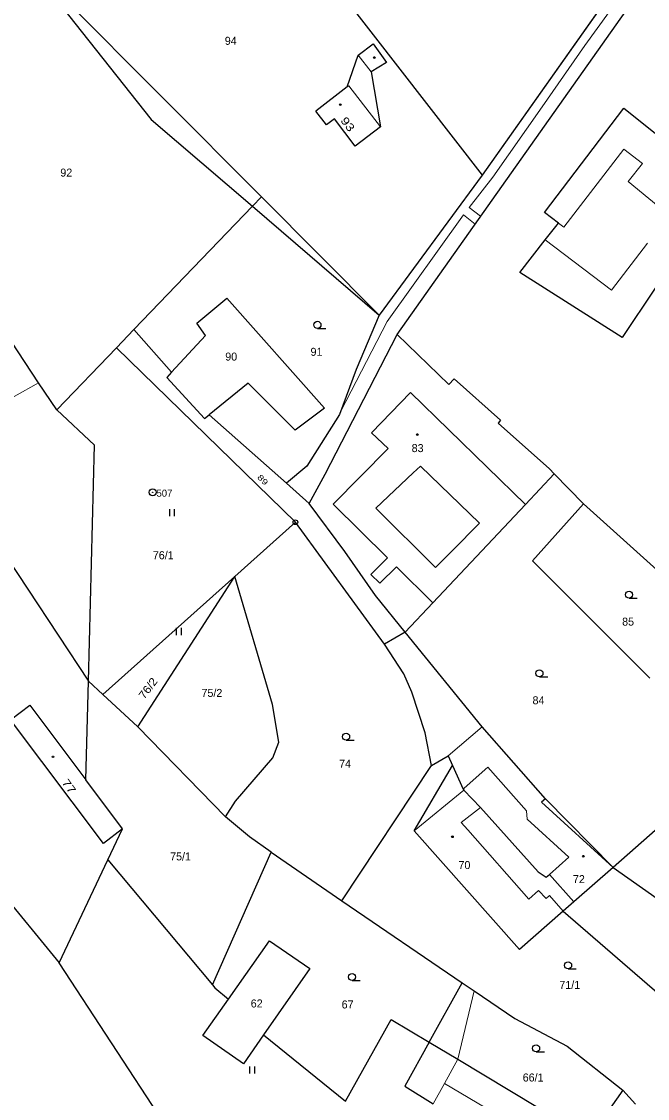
# Model space of a CAD drawing. Extents: x -504006 to -501322, y -1128098 to -1124665.
# Drawn here: x -502824.9 to -502691.9, y -1126531.9 to -1126303.1 of the extents above; entities that cross this region are included whole.
import ezdxf
from ezdxf.enums import TextEntityAlignment as Align

# ---------------------------------------------------------------- set-up
doc = ezdxf.new("R2010")
doc.units = 0
doc.header["$LTSCALE"] = 0.68
for name, color, linetype, lineweight in [('1', 7, 'Continuous', 25), ('13', 7, 'Continuous', 13), ('3', 7, 'Continuous', 25), ('4', 7, 'Continuous', 13), ('5', 7, 'Continuous', 25), ('8', 7, 'Continuous', 25)]:
    doc.layers.add(name, color=color, linetype=linetype, lineweight=lineweight)
doc.layers.add('2', color=7, linetype='Continuous')

msp = doc.modelspace()

# ---------------------------------------------------------------- linework, layer by layer
at = {"layer": '1'}
for p, q in [((-502765.38, -1126286.27), (-502727.05, -1126335.75)), ((-502824.6, -1126289.43), (-502797.35, -1126323.91)), ((-502745.09, -1126369.61), (-502691.94, -1126294.4)), ((-502699.22, -1126296.35), (-502727.05, -1126335.75)), ((-502821.24, -1126379.86), (-502870.11, -1126306.48)), ((-502753.34, -1126310.27), (-502750.18, -1126307.85)), ((-502750.18, -1126307.85), (-502747.34, -1126311.8)), ((-502755.67, -1126317), (-502753.34, -1126310.27)), ((-502747.34, -1126311.8), (-502750.64, -1126313.8)), ((-502750.64, -1126313.8), (-502748.65, -1126325.49)), ((-502755.67, -1126317), (-502762.37, -1126322.15)), ((-502760.1, -1126325.1), (-502762.37, -1126322.15)), ((-502713.8, -1126343.71), (-502696.91, -1126321.52)), ((-502696.91, -1126321.52), (-502675.99, -1126338.4)), ((-502797.35, -1126323.91), (-502775.83, -1126342.38)), ((-502758.41, -1126323.8), (-502760.1, -1126325.1)), ((-502753.97, -1126329.58), (-502758.41, -1126323.8)), ((-502748.65, -1126325.49), (-502753.97, -1126329.58)), ((-502727.05, -1126335.75), (-502748.9, -1126365.5)), ((-502801, -1126368.56), (-502775.83, -1126342.38)), ((-502775.83, -1126342.38), (-502748.9, -1126365.5)), ((-502710.8, -1126345.95), (-502713.8, -1126343.71)), ((-502713.68, -1126349.52), (-502710.8, -1126345.95)), ((-502944.94, -1126347.11), (-502816.86, -1126503.09)), ((-502719, -1126356.44), (-502713.68, -1126349.52)), ((-502697.31, -1126370.22), (-502719, -1126356.44)), ((-502787.61, -1126367.21), (-502781.27, -1126361.89)), ((-502781.27, -1126361.89), (-502760.54, -1126385.27)), ((-502690.31, -1126359.77), (-502697.31, -1126370.22)), ((-502748.9, -1126365.5), (-502753.78, -1126377.07)), ((-502804.71, -1126372.42), (-502801, -1126368.56)), ((-502801, -1126368.56), (-502792.99, -1126377.61)), ((-502785.82, -1126369.79), (-502787.61, -1126367.21)), ((-502792.99, -1126377.61), (-502785.82, -1126369.79)), ((-502760.39, -1126399.29), (-502745.09, -1126369.61)), ((-502745.09, -1126369.61), (-502734.11, -1126380.21)), ((-502804.71, -1126372.42), (-502817.4, -1126385.62)), ((-502766.7, -1126409.48), (-502804.71, -1126372.42)), ((-502792.99, -1126377.61), (-502794.01, -1126378.72)), ((-502753.78, -1126377.07), (-502757.3, -1126386.6)), ((-502817.4, -1126385.62), (-502821.24, -1126379.86)), ((-502794.01, -1126378.72), (-502786, -1126387.47)), ((-502776.76, -1126379.96), (-502784.99, -1126386.65)), ((-502766.74, -1126389.96), (-502776.76, -1126379.96)), ((-502734.11, -1126380.21), (-502733.01, -1126379.06)), ((-502733.01, -1126379.06), (-502723.17, -1126387.83)), ((-502809.37, -1126393.13), (-502817.4, -1126385.62)), ((-502786, -1126387.47), (-502784.99, -1126386.65)), ((-502784.99, -1126386.65), (-502768.58, -1126401.2)), ((-502760.54, -1126385.27), (-502766.74, -1126389.96)), ((-502757.3, -1126386.6), (-502764.3, -1126397.58)), ((-502723.17, -1126387.83), (-502723.62, -1126388.43)), ((-502723.62, -1126388.43), (-502712.76, -1126398.15)), ((-502844.04, -1126392.64), (-502810.65, -1126443.26)), ((-502810.65, -1126443.26), (-502809.37, -1126393.13)), ((-502764.3, -1126397.58), (-502768.58, -1126401.2)), ((-502712.76, -1126398.15), (-502711.72, -1126399.22)), ((-502763.76, -1126405.48), (-502760.39, -1126399.29)), ((-502711.72, -1126399.22), (-502717.8, -1126405.69)), ((-502711.72, -1126399.22), (-502705.53, -1126405.59)), ((-502768.58, -1126401.2), (-502763.76, -1126405.48)), ((-502756.18, -1126415.7), (-502763.76, -1126405.48)), ((-502717.8, -1126405.69), (-502737.48, -1126426.63)), ((-502705.53, -1126405.59), (-502716.32, -1126417.67)), ((-502705.53, -1126405.59), (-502687.79, -1126421.49)), ((-502779.58, -1126421.01), (-502766.7, -1126409.48)), ((-502747.8, -1126435.38), (-502766.7, -1126409.48)), ((-502749.69, -1126425.09), (-502756.18, -1126415.7)), ((-502716.32, -1126417.67), (-502691.44, -1126442.61)), ((-502807.59, -1126446.09), (-502779.58, -1126421.01)), ((-502800.13, -1126452.98), (-502779.58, -1126421.01)), ((-502771.54, -1126448.18), (-502779.58, -1126421.01)), ((-502743.35, -1126432.88), (-502749.69, -1126425.09)), ((-502737.48, -1126426.63), (-502743.35, -1126432.88)), ((-502743.35, -1126432.88), (-502747.8, -1126435.38)), ((-502727.02, -1126452.94), (-502743.35, -1126432.88)), ((-502743.69, -1126441.68), (-502747.8, -1126435.38)), ((-502741.96, -1126445.6), (-502743.69, -1126441.68)), ((-502811.18, -1126464.25), (-502810.65, -1126443.26)), ((-502810.65, -1126443.26), (-502807.59, -1126446.09)), ((-502807.59, -1126446.09), (-502800.13, -1126452.98)), ((-502739.12, -1126454.21), (-502741.96, -1126445.6)), ((-502827.19, -1126451.44), (-502823.08, -1126448.36)), ((-502823.08, -1126448.36), (-502811.18, -1126464.25)), ((-502770.19, -1126456.22), (-502771.54, -1126448.18)), ((-502807.45, -1126477.77), (-502827.19, -1126451.44)), ((-502800.13, -1126452.98), (-502781.55, -1126472.1)), ((-502713.6, -1126468.24), (-502727.02, -1126452.94)), ((-502737.81, -1126461.2), (-502739.12, -1126454.21)), ((-502771.51, -1126459.54), (-502770.19, -1126456.22)), ((-502779.44, -1126468.77), (-502771.51, -1126459.54)), ((-502737.81, -1126461.2), (-502734.26, -1126459.15)), ((-502734.26, -1126459.15), (-502733.34, -1126461.16)), ((-502756.85, -1126489.95), (-502737.81, -1126461.2)), ((-502741.45, -1126475.07), (-502733.34, -1126461.16)), ((-502733.34, -1126461.16), (-502731.05, -1126466.19)), ((-502803.39, -1126474.66), (-502811.18, -1126464.25)), ((-502731.05, -1126466.19), (-502730.93, -1126466.44)), ((-502730.93, -1126466.44), (-502727.39, -1126470.06)), ((-502781.55, -1126472.1), (-502779.44, -1126468.77)), ((-502713.6, -1126468.24), (-502714.44, -1126468.97)), ((-502714.44, -1126468.97), (-502699.2, -1126482.81)), ((-502682.88, -1126468.4), (-502699.2, -1126482.81)), ((-502727.39, -1126470.06), (-502715.11, -1126483.78)), ((-502776.47, -1126476.36), (-502781.55, -1126472.1)), ((-502803.39, -1126474.66), (-502807.45, -1126477.77)), ((-502806.5, -1126481.21), (-502803.39, -1126474.66)), ((-502771.85, -1126479.55), (-502776.47, -1126476.36)), ((-502719.08, -1126500.23), (-502741.45, -1126475.07)), ((-502784.28, -1126507.78), (-502771.85, -1126479.55)), ((-502771.85, -1126479.55), (-502756.85, -1126489.95)), ((-502816.86, -1126503.09), (-502806.5, -1126481.21)), ((-502806.5, -1126481.21), (-502784.28, -1126507.78)), ((-502699.2, -1126482.81), (-502707.55, -1126490.13)), ((-502699.2, -1126482.81), (-502676.74, -1126498.71)), ((-502715.11, -1126483.78), (-502713.43, -1126484.92)), ((-502713.43, -1126484.92), (-502712.75, -1126484.32)), ((-502712.75, -1126484.32), (-502707.55, -1126490.13)), ((-502756.85, -1126489.95), (-502731.3, -1126507.32)), ((-502709.81, -1126492.11), (-502719.08, -1126500.23)), ((-502707.55, -1126490.13), (-502709.81, -1126492.11)), ((-502709.81, -1126492.11), (-502664.03, -1126531.82)), ((-502780.88, -1126510.78), (-502772.21, -1126498.45)), ((-502772.21, -1126498.45), (-502763.62, -1126504.3)), ((-502792.14, -1126540.91), (-502816.86, -1126503.09)), ((-502763.62, -1126504.3), (-502773.44, -1126518.37)), ((-502784.28, -1126507.78), (-502783.78, -1126508.37)), ((-502783.78, -1126508.37), (-502780.88, -1126510.78)), ((-502738.28, -1126519.96), (-502731.3, -1126507.32)), ((-502731.3, -1126507.32), (-502728.74, -1126509.06)), ((-502728.74, -1126509.06), (-502720.12, -1126514.93)), ((-502786.35, -1126518.55), (-502780.88, -1126510.78)), ((-502756.08, -1126532.45), (-502746.39, -1126515.1)), ((-502746.39, -1126515.1), (-502738.28, -1126519.96)), ((-502720.12, -1126514.93), (-502709, -1126520.83)), ((-502777.75, -1126524.55), (-502786.35, -1126518.55)), ((-502773.44, -1126518.37), (-502777.75, -1126524.55)), ((-502773.44, -1126518.37), (-502756.08, -1126532.45)), ((-502738.28, -1126519.96), (-502743.42, -1126529.26)), ((-502738.28, -1126519.96), (-502732.23, -1126523.58)), ((-502709, -1126520.83), (-502697.16, -1126530.12)), ((-502732.23, -1126523.58), (-502707.62, -1126538.32)), ((-502743.42, -1126529.26), (-502737.43, -1126533.08)), ((-502697.16, -1126530.12), (-502711.14, -1126549.85)), ((-502697.16, -1126530.12), (-502694.48, -1126533.09))]:
    msp.add_line(p, q, dxfattribs=at)
at = {"layer": '13'}
msp.add_lwpolyline([(-502699.22, -1126296.35), (-502727.05, -1126335.75), (-502748.9, -1126365.5), (-502753.78, -1126377.07), (-502757.05, -1126385.92), (-502747.19, -1126366.84), (-502731.03, -1126344.19), (-502728.5, -1126346.14), (-502727.35, -1126344.5), (-502729.82, -1126342.6), (-502724.73, -1126336.16), (-502714.26, -1126321.27), (-502705.19, -1126308.23), (-502697.38, -1126297.31)], dxfattribs=at)
at = {"layer": '3'}
for p, q in [((-502762.013, -1126368.31), (-502760.263, -1126368.31)), ((-502793.351, -1126408.19), (-502793.351, -1126406.69)), ((-502792.35, -1126408.19), (-502792.35, -1126406.69)), ((-502695.833, -1126425.63), (-502694.083, -1126425.63)), ((-502791.921, -1126433.45), (-502791.921, -1126431.95)), ((-502790.92, -1126433.45), (-502790.92, -1126431.95)), ((-502714.863, -1126442.34), (-502713.113, -1126442.34)), ((-502755.933, -1126455.8), (-502754.183, -1126455.8)), ((-502708.783, -1126504.38), (-502707.033, -1126504.38)), ((-502754.663, -1126506.85), (-502752.913, -1126506.85)), ((-502715.573, -1126522), (-502713.823, -1126522)), ((-502776.341, -1126526.59), (-502776.341, -1126525.09)), ((-502775.34, -1126526.59), (-502775.34, -1126525.09))]:
    msp.add_line(p, q, dxfattribs=at)
for centre in [(-502762.0129, -1126367.5598), (-502695.8329, -1126424.8798), (-502714.8629, -1126441.5898), (-502755.9329, -1126455.0498), (-502708.7829, -1126503.6298), (-502754.6629, -1126506.0998), (-502715.5729, -1126521.2498)]:
    msp.add_circle(centre, 0.75, dxfattribs=at)
at = {"layer": '4'}
for p, q in [((-502773.91, -1126340.37), (-502824.6, -1126289.43)), ((-502750.64, -1126313.8), (-502753.34, -1126310.27)), ((-502755.67, -1126317), (-502755.36, -1126316.76)), ((-502755.36, -1126316.76), (-502748.65, -1126325.49)), ((-502696.91, -1126330.23), (-502709.67, -1126346.79)), ((-502692.96, -1126333.27), (-502696.91, -1126330.23)), ((-502696.05, -1126337.11), (-502692.96, -1126333.27)), ((-502687.21, -1126344.31), (-502696.05, -1126337.11)), ((-502773.91, -1126340.37), (-502775.83, -1126342.38)), ((-502748.9, -1126365.5), (-502773.91, -1126340.37)), ((-502709.67, -1126346.79), (-502710.8, -1126345.95)), ((-502713.68, -1126349.52), (-502699.53, -1126360.17)), ((-502699.53, -1126360.17), (-502691.91, -1126350.23)), ((-502844.04, -1126392.64), (-502821.77, -1126380.16)), ((-502821.24, -1126379.86), (-502821.77, -1126380.16)), ((-502750.5, -1126390.51), (-502742.28, -1126381.93)), ((-502742.28, -1126381.93), (-502717.8, -1126405.69)), ((-502747.02, -1126393.86), (-502750.5, -1126390.51)), ((-502758.71, -1126405.64), (-502747.02, -1126393.86)), ((-502741.65, -1126399.01), (-502740.14, -1126397.58)), ((-502740.14, -1126397.58), (-502727.6, -1126409.68)), ((-502749.59, -1126406.51), (-502741.65, -1126399.01)), ((-502747.16, -1126417.06), (-502758.71, -1126405.64)), ((-502736.92, -1126419.13), (-502749.59, -1126406.51)), ((-502727.79, -1126409.87), (-502733.18, -1126415.33)), ((-502727.6, -1126409.68), (-502727.79, -1126409.87)), ((-502733.18, -1126415.33), (-502736.92, -1126419.13)), ((-502750.68, -1126420.6), (-502747.16, -1126417.06)), ((-502745.25, -1126418.95), (-502748.77, -1126422.47)), ((-502737.48, -1126426.63), (-502745.25, -1126418.95)), ((-502748.77, -1126422.47), (-502750.68, -1126420.6)), ((-502734.26, -1126459.15), (-502727.02, -1126452.94)), ((-502725.82, -1126461.55), (-502730.83, -1126466)), ((-502717.63, -1126470.81), (-502725.82, -1126461.55)), ((-502741.45, -1126475.07), (-502730.93, -1126466.44)), ((-502730.83, -1126466), (-502731.05, -1126466.19)), ((-502699.2, -1126482.81), (-502713.6, -1126468.24)), ((-502727.39, -1126470.06), (-502731.49, -1126473.28)), ((-502717.49, -1126472.56), (-502717.63, -1126470.81)), ((-502731.49, -1126473.28), (-502730.1, -1126474.84)), ((-502708.59, -1126480.68), (-502717.49, -1126472.56)), ((-502730.1, -1126474.84), (-502717.09, -1126489.54)), ((-502712.75, -1126484.32), (-502708.59, -1126480.68)), ((-502717.09, -1126489.54), (-502715.06, -1126487.72)), ((-502715.06, -1126487.72), (-502713.41, -1126489.41)), ((-502713.41, -1126489.41), (-502712.74, -1126488.82)), ((-502712.74, -1126488.82), (-502709.81, -1126492.11)), ((-502732.23, -1126523.58), (-502728.74, -1126509.06)), ((-502735.04, -1126528.73), (-502732.23, -1126523.58)), ((-502735.04, -1126528.73), (-502737.43, -1126533.08)), ((-502714.9, -1126540.61), (-502735.04, -1126528.73))]:
    msp.add_line(p, q, dxfattribs=at)
at = {"layer": '5'}
for centre in [(-502749.9468, -1126310.7792), (-502757.1668, -1126320.7692), (-502740.8068, -1126390.8692), (-502818.1768, -1126459.3292), (-502733.3368, -1126476.3192), (-502705.5568, -1126480.4492)]:
    msp.add_circle(centre, 0.175, dxfattribs=at)
at = {"layer": '8'}
for centre, radius in [((-502797.01, -1126403.1398), 0.75), ((-502797.01, -1126403.1398), 0.03), ((-502766.7, -1126409.4799), 0.5), ((-502766.7, -1126409.4799), 0.0303)]:
    msp.add_circle(centre, radius, dxfattribs=at)

# ---------------------------------------------------------------- texts
at = {"layer": '2'}
for s, p in [('94', (-502780.429, -1126308.065)), ('92', (-502815.359, -1126336.065)), ('91', (-502762.219, -1126374.135)), ('90', (-502780.329, -1126375.155)), ('83', (-502740.739, -1126394.595)), ('76/1', (-502794.769, -1126417.355)), ('85', (-502696.039, -1126431.455)), ('75/2', (-502784.429, -1126446.605)), ('84', (-502715.069, -1126448.165)), ('74', (-502756.139, -1126461.625)), ('75/1', (-502791.089, -1126481.335)), ('70', (-502730.799, -1126483.175)), ('72', (-502706.489, -1126486.155)), ('71/1', (-502708.429, -1126508.635)), ('62', (-502774.919, -1126512.575)), ('67', (-502755.609, -1126512.785)), ('66/1', (-502716.209, -1126528.305))]:
    msp.add_text(s, height=1.7, dxfattribs=at).set_placement(p, align=Align.CENTER)
for s, height, rotation, width, p in [('93', 1.7, 307, 1.25, (-502756.2629, -1126325.4465)), ('89', 1.2, 315, 1.35, (-502774.0458, -1126400.9072)), ('76/2', 1.7, 53, 1.1, (-502797.3143, -1126445.275)), ('77', 1.7, 306, 1.25, (-502815.4781, -1126466.0934))]:
    msp.add_text(s, height=height, rotation=rotation, dxfattribs=dict(at, width=width)).set_placement(p, align=Align.CENTER)
at = {"layer": '8'}
msp.add_text('507', height=1.5, dxfattribs=at).set_placement((-502792.839, -1126404.065), align=Align.RIGHT)

doc.saveas('drawing.dxf')
